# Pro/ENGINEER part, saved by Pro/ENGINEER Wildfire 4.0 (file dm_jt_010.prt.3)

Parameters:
  METRIC = "NO"

Other parameters: PITCH, DRILL_POINT_ANGLE, DRILL_DEPTH, DRILL_DIAMETER, THREAD_DIAMETER, THREADS_PER_INCH, THREAD_DEPTH, THREAD_LENGTH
